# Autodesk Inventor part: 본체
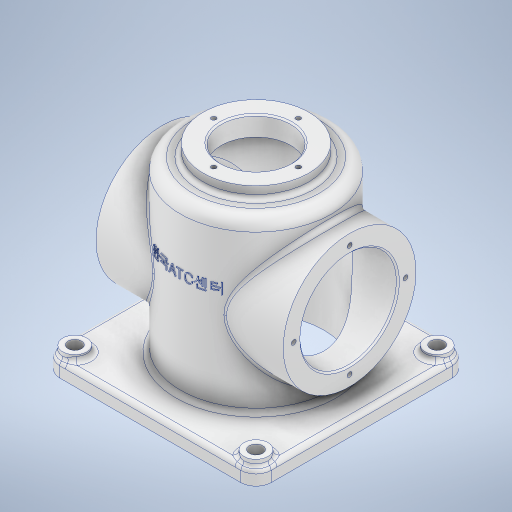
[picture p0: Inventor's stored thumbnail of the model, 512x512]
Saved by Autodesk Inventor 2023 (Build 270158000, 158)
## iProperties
Created: 2025-05
Part Number: 본체
Material: 알루미늄 6061
Document SubType Name: Modeling
Designer: ADMIN_PC
Mass: 1131.69 g
Surface Area: 1201.66 cm^2
Volume: 419.146 cm^3
Density: 2.7 g/cm^3
Appearance: 알루미늄 - 평지
Author: ADMIN_PC
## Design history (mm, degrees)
sketch "스케치1"
  geometry: L1 (-70, 70)-(70, 70); L2 (70, 70)-(70, -70); L3 (70, -70)-(-70, -70); L4 (-70, -70)-(-70, 70); L5 (-70, 70)-(70, -70); L6 (70, 70)-(-70, -70); 1 further point
  constraints: 12 end point, 2 midpoint, 2 parallel, 1 horizontal, 1 perpendicular
  dimensions: "d0" = 140 distance of L2.end L3.end; "d1" = 140 distance of L1.end L2.end
extrude "돌출1" new body sketch "스케치1" distance "d2" = 10; taper "d3" = 0 deg
sketch "스케치2"
  geometry: C1 r 50 at (0, 0); 1 further point
  constraints: 1 centre point, 1 coincident
  dimensions: "d4" = 100 diameter of C1
extrude "돌출2" join sketch "스케치2" distance "d5" = 112; taper "d6" = 0 deg
sketch "스케치3"
  geometry: C1 r 35 at (0, 0); 1 further point
  constraints: 1 centre point, 1 coincident
  dimensions: "d7" = 70 diameter of C1
extrude "돌출3" join sketch "스케치3" distance "d8" = 8; taper "d9" = 0 deg
node "작업 평면1"
sketch "스케치5"
  geometry: L1 (-26, 0)-(156, 0) reference; L2 (0, 0)-(65, 0); C1 r 44 at (65, 0)
  constraints: 2 end point, 1 centre point, 1 coincident, 1 midpoint
  dimensions: "d11" = 65 distance of L2.start L2.end; "d12" = 88 diameter of C1
extrude "돌출4" join sketch "스케치5" stored distance "d13" = 8; taper "d14" = 0 deg
sketch "스케치6" dims "d15" = 74
  geometry: L1 (0, -91)-(0, 91) reference; C1 r 44 at (0, 0) reference; 3 further points
  constraints: 1 coincident, 1 point on line, 1 vertical alignment, 2 other
hole "구멍1" sketch "스케치6" at (0, 37) diameter "d16" = 3.242; stored, may be unused: countersink angle "d20" = 90 deg, drill point angle "d22" = 118 deg; dims "d17" = 8, "d18" = 4, "d19" = 2, "d21" = 10
sketch "스케치7"
  geometry: C1 r 44 at (0, 0) reference; C2 r 32 at (0, 0); 1 further point
  constraints: 1 centre point, 1 coincident
  dimensions: "d26" = 64 diameter of C2
extrude "돌출5" cut sketch "스케치7" stored distance "d27" = 10; taper "d28" = 0 deg
sketch "스케치8"
  geometry: L1 (50, 10)-(50, 122) reference; L2 (-50, 10)-(-50, 122) reference; L3 (50, 122)-(-50, 122) reference; L4 (35, 130)-(-35, 130) reference; L5 (-35, 122)-(-35, 130) reference; L6 (35, 122)-(35, 130) reference; L7 (-35, 122)-(35, 122) reference; L8 (-70, 0)-(-70, 10) reference; L9 (70, 0)-(70, 10) reference; L10 (45, 10)-(45, 117); L11 (45, 0)-(45, 10); L12 (0, 117)-(0, 0); L13 (70, 0)-(-70, 0) reference; L14 (45, 0)-(0, 0); L15 (0, 117)-(45, 117)
  constraints: 10 end point, 3 perpendicular, 1 parallel
  dimensions: "d29" = 5 distance between parallel lines of L1 L10; "d30" = 117 distance of L12.start L12.end
revolve "회전1" sketch "스케치8" stored, may be unused: angle "d31" = 90 deg
sketch "스케치9" dims "d32" = 56
  geometry: L1 (0, 98)-(0, -98) reference; 3 further points
  constraints: 1 coincident, 1 point on line, 1 vertical alignment, 2 other
hole "구멍2" sketch "스케치9" at (0, 28) diameter "d33" = 3.242; stored, may be unused: countersink angle "d37" = 90 deg, drill point angle "d39" = 118 deg; dims "d34" = 8, "d35" = 4, "d36" = 2, "d38" = 10
sketch "스케치10"
  geometry: C1 r 35 at (0, 0) reference; C2 r 23 at (0, 0); 1 further point
  constraints: 1 centre point, 1 coincident
  dimensions: "d43" = 46 diameter of C2
extrude "돌출6" cut sketch "스케치10" stored distance "d44" = 10; taper "d45" = 0 deg
fillet "모깎기1" dims "d46" = 8
chamfer "모따기1" distance "d47" = 1; stored, may be unused: second distance "d48" = 2, angle "d49" = 45 deg
fillet "모깎기2" dims "d50" = 3
fillet "모깎기3" dims "d51" = 10
sketch "스케치11"
  geometry: C1 r 8 at (-60, 60); C2 r 8 at (60, 60); C3 r 8 at (60, -60); C4 r 8 at (-60, -60); A1 r 10 centre (-60, 60) between (-60, 70) and (-70, 60) reference; A2 r 10 centre (60, 60) between (70, 60) and (60, 70) reference; A3 r 10 centre (60, -60) between (60, -70) and (70, -60) reference; A4 r 10 centre (-60, -60) between (-70, -60) and (-60, -70) reference; 1 further point
  constraints: 4 centre point, 4 coincident
  dimensions: "d52" = 16 diameter of C1; "d53" = 16 diameter of C2; "d54" = 16 diameter of C3; "d55" = 16 diameter of C4
extrude "돌출7" join sketch "스케치11" distance "d56" = 4; taper "d57" = 0 deg
sketch "스케치12"
  geometry: C1 r 8 at (0, 0) reference; C2 r 4.5 at (0, 0); C3 r 8 at (120, 0) reference; C4 r 4.5 at (120, 0); C5 r 8 at (120, 120) reference; C6 r 4.5 at (120, 120); C7 r 8 at (0, 120) reference; C8 r 4.5 at (0, 120); 1 further point
  constraints: 4 centre point, 4 coincident
  dimensions: "d60" = 9 diameter of C2; "d61" = 9 diameter of C4; "d62" = 9 diameter of C6; "d63" = 9 diameter of C8
extrude "돌출8" cut sketch "스케치12" extent not by distance; stored distance "d64" = 0; taper "d65" = 0 deg
node "작업 평면2"
sketch "스케치13" dims "d11" = 65, "d12" = 88
  geometry: L1 (-60, 0)-(60, 0) reference; 2 further points
  constraints: 1 other
  dimensions: "d67" = 80 distance from line of L1 point (0, 80)
feature "엠보싱1" sketch "스케치13" dims "d0" = 140, "d1" = 140, "d11" = 65, "d12" = 88, "d68" = 0.5, "d69" = 0
fillet "모깎기6" dims "d70" = 3
fillet "모깎기7" dims "d71" = 3
fillet "모깎기9" dims "d76" = 3
feature "Ј耀Њ耀Ќ耀Ў耀А耀В耀Д耀Ж耀" dims "d0" = 140, "d1" = 140, "d2" = 10, "d3" = 0, "d4" = 100, "d5" = 112, "d6" = 0, "d7" = 70, "d8" = 8, "d9" = 0, "d10" = 62, "d11" = 65, "d12" = 88, "d13" = 8, "d14" = 0, "d15" = 74, "d16" = 3.242, "d17" = 8, "d18" = 4, "d19" = 2, "d20" = 90 deg, "d21" = 10, "d22" = 118 deg, "d23" = 40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
node "솔리드1"
mirror "미러1"
pattern_circular "원형 패턴1" dims angle "d24" = 360 deg
mirror "미러2"
pattern_circular "원형 패턴2" dims angle "d41" = 360 deg
feature "A9D066F2-1C7D-4E18-AEED-F7BC21143FA4" dims "d16" = 3.242, "d17" = 8, "d18" = 4, "d19" = 2, "d20" = 90 deg, "d21" = 10, "d22" = 118 deg
